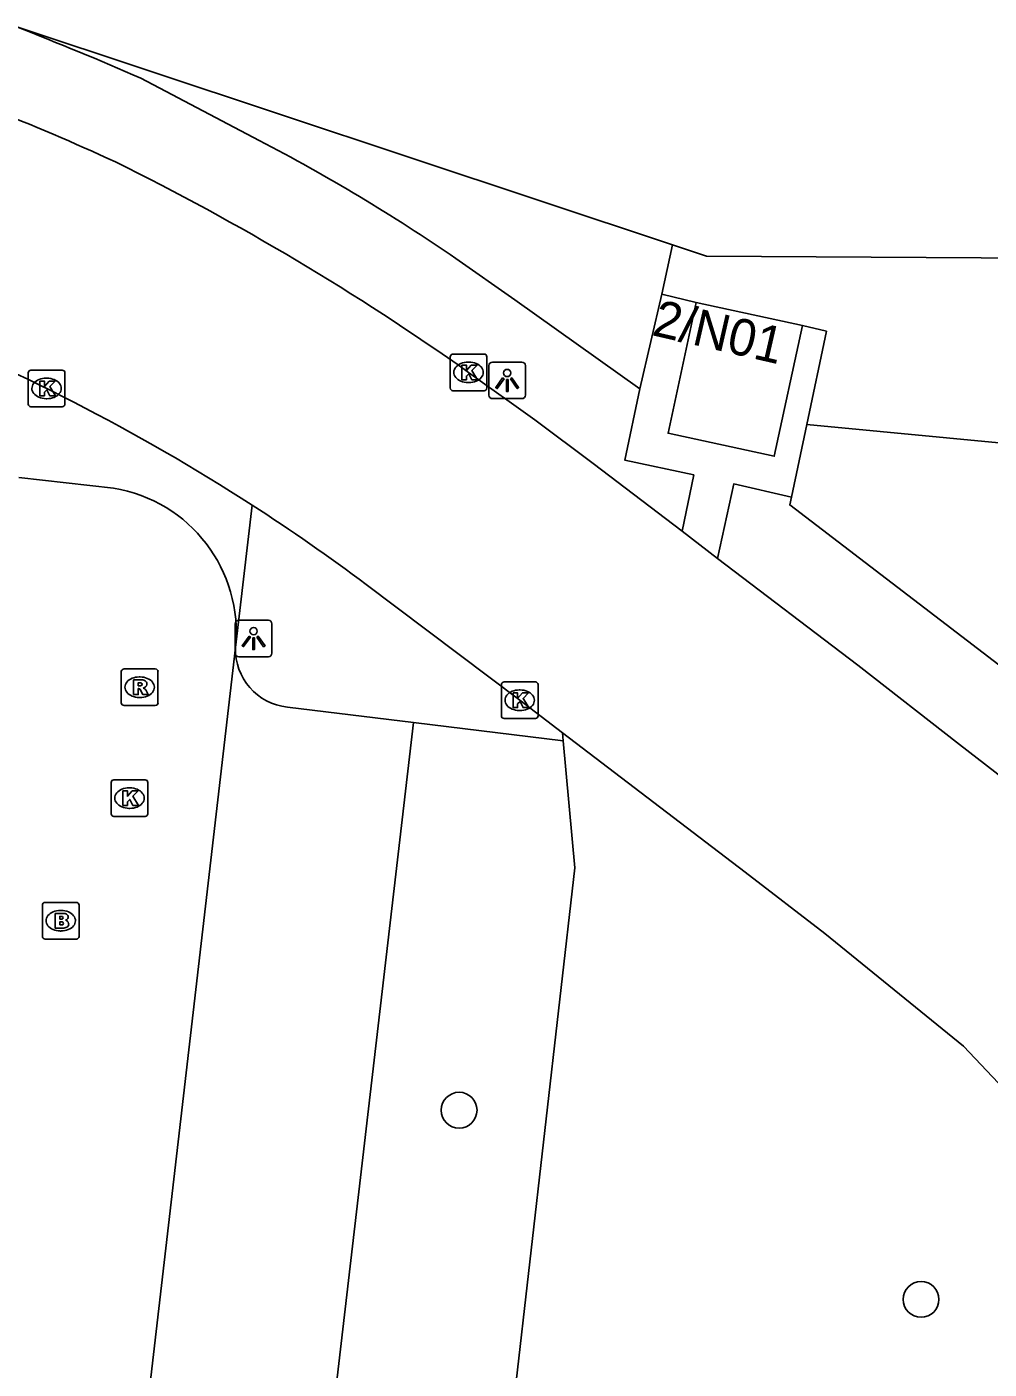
# Model space of a CAD drawing. Extents: x 161243 to 161752, y 384138 to 384885.
# Drawn here: x 161599.29 to 161625.54, y 384599.27 to 384635.9 of the extents above; entities that cross this region are included whole.
import ezdxf

# ---------------------------------------------------------------- set-up
doc = ezdxf.new("R2010")
doc.units = 0
for name, color, linetype in [('IMGEO_Boom', 7, 'Continuous'), ('IMGEO_Brandkraan', 7, 'Continuous'), ('IMGEO_Groenvoorziening', 7, 'Continuous'), ('IMGEO_Hek', 7, 'Continuous'), ('IMGEO_Kolk', 7, 'Continuous'), ('IMGEO_Lichtpunt', 7, 'Continuous'), ('IMGEO_Pand', 7, 'Continuous'), ('IMGEO_Pand_nummerreeks', 7, 'Continuous'), ('IMGEO_Parkeervlak_open', 7, 'Continuous'), ('IMGEO_Rijbaan_lokaal_open', 7, 'Continuous'), ('IMGEO_Rioolput', 7, 'Continuous'), ('IMGEO_Voetpad_open', 7, 'Continuous')]:
    doc.layers.add(name, color=color, linetype=linetype)

msp = doc.modelspace()

# ---------------------------------------------------------------- linework, layer by layer
at = {"layer": 'IMGEO_Boom'}
for centre in [(161611.081, 384606.338), (161623.685, 384601.176)]:
    msp.add_circle(centre, 0.489, dxfattribs=at)
at = {"layer": 'IMGEO_Brandkraan'}
for p, q in [((161599.787, 384612.008), (161600.639, 384612.008)), ((161599.712, 384611.082), (161599.712, 384611.934)), ((161600.2, 384611.788), (161600.225, 384611.788)), ((161600.713, 384611.934), (161600.713, 384611.082)), ((161600.639, 384611.008), (161599.787, 384611.008)), ((161600.223, 384611.228), (161600.198, 384611.228))]:
    msp.add_line(p, q, dxfattribs=at)
for points in [[(161599.787, 384612.008), (161600.639, 384612.008)], [(161599.712, 384611.082), (161599.712, 384611.934)], [(161600.06, 384611.708), (161600.06, 384611.308), (161600.273, 384611.308)], [(161600.291, 384611.708), (161600.06, 384611.708)], [(161600.239, 384611.627), (161600.185, 384611.627), (161600.185, 384611.551)], [(161600.713, 384611.934), (161600.713, 384611.082)], [(161600.185, 384611.551), (161600.238, 384611.551)], [(161600.247, 384611.475), (161600.185, 384611.475), (161600.185, 384611.394)], [(161600.185, 384611.394), (161600.247, 384611.394)], [(161600.639, 384611.008), (161599.787, 384611.008)]]:
    msp.add_lwpolyline(points, dxfattribs=at)
for centre, radius, start, end in [((161599.789, 384611.932), 0.0765, 91.552, 178.448), ((161599.789, 384611.932), 0.0765, 91.552, 178.448), ((161600.637, 384611.932), 0.0765, 1.552, 88.448), ((161600.637, 384611.932), 0.0765, 1.552, 88.448), ((161600.24, 384611.589), 0.0379, 267.8285, 90.9355), ((161600.295, 384611.563), 0.145, 59.4692, 91.5367), ((161600.32, 384611.61), 0.0922, 285.5137, 58.1501), ((161600.248, 384611.434), 0.0404, 269.8759, 90.5077), ((161600.279, 384611.559), 0.251, 268.6676, 293.5347), ((161600.325, 384611.418), 0.105, 301.3115, 78.989), ((161599.789, 384611.084), 0.0765, 181.552, 268.448), ((161599.789, 384611.084), 0.0765, 181.552, 268.448), ((161600.637, 384611.084), 0.0765, 271.552, 358.448), ((161600.637, 384611.084), 0.0765, 271.552, 358.448)]:
    msp.add_arc(centre, radius, start, end, dxfattribs=at)
for centre, major_axis, ratio, start_param, end_param in [((161600.199, 384611.508), (-0.387, 0.002), 0.722429, 4.712389, 7.853982), ((161600.224, 384611.508), (-0.39, 0.002), 0.717154, 1.570796, 4.712389)]:
    msp.add_ellipse(centre, major_axis=major_axis, ratio=ratio, start_param=start_param, end_param=end_param, dxfattribs=at)
at = {"layer": 'IMGEO_Groenvoorziening'}
for points in [[(161616.903, 384629.956), (161599.011, 384635.9)], [(161616.611, 384628.604), (161616.903, 384629.956)], [(161649.293, 384629.449), (161617.828, 384629.647), (161616.903, 384629.956)], [(161620.569, 384625.051), (161632.188, 384623.942), (161646.68, 384624.454)], [(161605.435, 384622.848), (161604.979, 384618.961)], [(161613.925, 384616.415), (161609.841, 384616.919)], [(161612.189, 384595.037), (161614.238, 384612.956), (161613.925, 384616.415)], [(161613.925, 384616.415), (161613.905, 384616.634)]]:
    msp.add_lwpolyline(points, dxfattribs=at)
at = {"layer": 'IMGEO_Hek'}
for points in [[(161599.011, 384635.9), (161616.903, 384629.956)], [(161616.903, 384629.956), (161617.828, 384629.647), (161649.293, 384629.449)]]:
    msp.add_lwpolyline(points, dxfattribs=at)
at = {"layer": 'IMGEO_Kolk'}
for p, q in [((161610.838, 384626.046), (161610.838, 384626.898)), ((161610.913, 384626.972), (161611.765, 384626.972)), ((161611.326, 384626.752), (161611.351, 384626.752)), ((161611.839, 384626.898), (161611.839, 384626.046)), ((161599.325, 384625.607), (161599.325, 384626.459)), ((161599.4, 384626.533), (161600.252, 384626.533)), ((161599.813, 384626.313), (161599.838, 384626.313)), ((161600.326, 384626.459), (161600.326, 384625.607)), ((161611.765, 384625.972), (161610.913, 384625.972)), ((161611.349, 384626.192), (161611.324, 384626.192)), ((161600.252, 384625.533), (161599.4, 384625.533)), ((161599.836, 384625.753), (161599.811, 384625.753)), ((161612.235, 384617.1), (161612.235, 384617.952)), ((161612.31, 384618.026), (161613.162, 384618.026)), ((161613.236, 384617.952), (161613.236, 384617.1)), ((161612.723, 384617.806), (161612.748, 384617.806)), ((161612.746, 384617.246), (161612.721, 384617.246)), ((161613.162, 384617.026), (161612.31, 384617.026)), ((161601.588, 384614.428), (161601.588, 384615.28)), ((161601.663, 384615.354), (161602.515, 384615.354)), ((161602.589, 384615.28), (161602.589, 384614.428)), ((161602.076, 384615.134), (161602.101, 384615.134)), ((161602.099, 384614.574), (161602.074, 384614.574)), ((161602.515, 384614.354), (161601.663, 384614.354))]:
    msp.add_line(p, q, dxfattribs=at)
for points in [[(161610.838, 384626.046), (161610.838, 384626.898)], [(161610.913, 384626.972), (161611.765, 384626.972)], [(161611.159, 384626.672), (161611.282, 384626.672), (161611.282, 384626.521), (161611.412, 384626.672), (161611.576, 384626.672), (161611.43, 384626.521), (161611.583, 384626.272), (161611.431, 384626.272), (161611.346, 384626.436), (161611.282, 384626.369), (161611.282, 384626.272), (161611.159, 384626.272), (161611.159, 384626.672)], [(161611.839, 384626.898), (161611.839, 384626.046)], [(161599.325, 384625.607), (161599.325, 384626.459)], [(161599.4, 384626.533), (161600.252, 384626.533)], [(161600.326, 384626.459), (161600.326, 384625.607)], [(161599.646, 384626.233), (161599.769, 384626.233), (161599.769, 384626.082), (161599.899, 384626.233), (161600.063, 384626.233), (161599.917, 384626.082), (161600.07, 384625.833), (161599.918, 384625.833), (161599.833, 384625.997), (161599.769, 384625.93), (161599.769, 384625.833), (161599.646, 384625.833), (161599.646, 384626.233)], [(161611.765, 384625.972), (161610.913, 384625.972)], [(161600.252, 384625.533), (161599.4, 384625.533)], [(161612.235, 384617.1), (161612.235, 384617.952)], [(161612.31, 384618.026), (161613.162, 384618.026)], [(161613.236, 384617.952), (161613.236, 384617.1)], [(161612.556, 384617.726), (161612.679, 384617.726), (161612.679, 384617.575), (161612.809, 384617.726), (161612.973, 384617.726), (161612.827, 384617.575), (161612.98, 384617.326), (161612.828, 384617.326), (161612.743, 384617.49), (161612.679, 384617.423), (161612.679, 384617.326), (161612.556, 384617.326), (161612.556, 384617.726)], [(161613.162, 384617.026), (161612.31, 384617.026)], [(161601.588, 384614.428), (161601.588, 384615.28)], [(161601.663, 384615.354), (161602.515, 384615.354)], [(161602.589, 384615.28), (161602.589, 384614.428)], [(161601.909, 384615.054), (161602.032, 384615.054), (161602.032, 384614.903), (161602.162, 384615.054), (161602.326, 384615.054), (161602.18, 384614.903), (161602.333, 384614.654), (161602.181, 384614.654), (161602.096, 384614.818), (161602.032, 384614.751), (161602.032, 384614.654), (161601.909, 384614.654), (161601.909, 384615.054)], [(161602.515, 384614.354), (161601.663, 384614.354)]]:
    msp.add_lwpolyline(points, dxfattribs=at)
for centre, start, end in [((161610.915, 384626.896), 91.552, 178.448), ((161610.915, 384626.896), 91.552, 178.448), ((161611.763, 384626.896), 1.552, 88.448), ((161611.763, 384626.896), 1.552, 88.448), ((161599.402, 384626.457), 91.552, 178.448), ((161599.402, 384626.457), 91.552, 178.448), ((161600.25, 384626.457), 1.552, 88.448), ((161600.25, 384626.457), 1.552, 88.448), ((161610.915, 384626.048), 181.552, 268.448), ((161610.915, 384626.048), 181.552, 268.448), ((161611.763, 384626.048), 271.552, 358.448), ((161611.763, 384626.048), 271.552, 358.448), ((161599.402, 384625.609), 181.552, 268.448), ((161599.402, 384625.609), 181.552, 268.448), ((161600.25, 384625.609), 271.552, 358.448), ((161600.25, 384625.609), 271.552, 358.448), ((161612.312, 384617.95), 91.552, 178.448), ((161612.312, 384617.95), 91.552, 178.448), ((161613.16, 384617.95), 1.552, 88.448), ((161613.16, 384617.95), 1.552, 88.448), ((161612.312, 384617.102), 181.552, 268.448), ((161612.312, 384617.102), 181.552, 268.448), ((161613.16, 384617.102), 271.552, 358.448), ((161613.16, 384617.102), 271.552, 358.448), ((161601.665, 384615.278), 91.552, 178.448), ((161601.665, 384615.278), 91.552, 178.448), ((161602.513, 384615.278), 1.552, 88.448), ((161602.513, 384615.278), 1.552, 88.448), ((161601.665, 384614.43), 181.552, 268.448), ((161601.665, 384614.43), 181.552, 268.448), ((161602.513, 384614.43), 271.552, 358.448), ((161602.513, 384614.43), 271.552, 358.448)]:
    msp.add_arc(centre, 0.0765, start, end, dxfattribs=at)
for centre, major_axis, ratio, start_param, end_param in [((161611.325, 384626.472), (-0.387, 0.002), 0.722429, 4.712389, 7.853982), ((161611.35, 384626.472), (-0.39, 0.002), 0.717154, 1.570796, 4.712389), ((161599.812, 384626.033), (-0.387, 0.002), 0.722429, 4.712389, 7.853982), ((161599.837, 384626.033), (-0.39, 0.002), 0.717154, 1.570796, 4.712389), ((161612.722, 384617.526), (-0.387, 0.002), 0.722429, 4.712389, 7.853982), ((161612.747, 384617.526), (-0.39, 0.002), 0.717154, 1.570796, 4.712389), ((161602.075, 384614.854), (-0.387, 0.002), 0.722429, 4.712389, 7.853982), ((161602.1, 384614.854), (-0.39, 0.002), 0.717154, 1.570796, 4.712389)]:
    msp.add_ellipse(centre, major_axis=major_axis, ratio=ratio, start_param=start_param, end_param=end_param, dxfattribs=at)
at = {"layer": 'IMGEO_Lichtpunt'}
for p, q in [((161611.895, 384626.657), (161611.895, 384625.85)), ((161611.895, 384626.657), (161611.895, 384625.85)), ((161612.797, 384626.752), (161611.989, 384626.752)), ((161612.797, 384626.752), (161611.989, 384626.752)), ((161612.891, 384625.85), (161612.891, 384626.657)), ((161612.891, 384625.85), (161612.891, 384626.657)), ((161611.989, 384625.756), (161612.797, 384625.756)), ((161611.989, 384625.756), (161612.797, 384625.756)), ((161605.877, 384619.708), (161605.069, 384619.708)), ((161605.877, 384619.708), (161605.069, 384619.708)), ((161604.975, 384619.613), (161604.975, 384618.806)), ((161604.975, 384619.613), (161604.975, 384618.806)), ((161605.971, 384618.806), (161605.971, 384619.613)), ((161605.971, 384618.806), (161605.971, 384619.613)), ((161605.069, 384618.712), (161605.877, 384618.712)), ((161605.069, 384618.712), (161605.877, 384618.712))]:
    msp.add_line(p, q, dxfattribs=at)
for points in [[(161612.269, 384626.321), (161612.308, 384626.293), (161612.12, 384626.031), (161612.082, 384626.058), (161612.269, 384626.321)], [(161612.371, 384626.273), (161612.418, 384626.273), (161612.418, 384625.951), (161612.371, 384625.951), (161612.371, 384626.273)], [(161612.481, 384626.293), (161612.519, 384626.32), (161612.706, 384626.058), (161612.667, 384626.03), (161612.481, 384626.293)], [(161605.349, 384619.277), (161605.388, 384619.249), (161605.2, 384618.987), (161605.162, 384619.014), (161605.349, 384619.277)], [(161605.451, 384619.229), (161605.498, 384619.229), (161605.498, 384618.907), (161605.451, 384618.907), (161605.451, 384619.229)], [(161605.561, 384619.249), (161605.599, 384619.276), (161605.786, 384619.014), (161605.747, 384618.986), (161605.561, 384619.249)]]:
    msp.add_lwpolyline(points, dxfattribs=at)
for centre in [(161612.394, 384626.455), (161605.474, 384619.411)]:
    msp.add_circle(centre, 0.0994, dxfattribs=at)
for centre, start, end in [((161611.989, 384626.657), 90, 180), ((161611.989, 384626.657), 90, 180), ((161612.797, 384626.657), 0, 90), ((161612.797, 384626.657), 0, 90), ((161611.989, 384625.85), 180, 270), ((161611.989, 384625.85), 180, 270), ((161612.797, 384625.85), 270, 0), ((161612.797, 384625.85), 270, 360), ((161605.069, 384619.613), 90, 180), ((161605.069, 384619.613), 90, 180), ((161605.877, 384619.613), 0, 90), ((161605.877, 384619.613), 0, 90), ((161605.069, 384618.806), 180, 270), ((161605.069, 384618.806), 180, 270), ((161605.877, 384618.806), 270, 0), ((161605.877, 384618.806), 270, 360)]:
    msp.add_arc(centre, 0.0946, start, end, dxfattribs=at)
at = {"layer": 'IMGEO_Pand'}
for points in [[(161620.45, 384627.751), (161619.679, 384624.183), (161616.782, 384624.81), (161617.553, 384628.377)], [(161617.553, 384628.377), (161620.45, 384627.751)]]:
    msp.add_lwpolyline(points, dxfattribs=at)
at = {"layer": 'IMGEO_Parkeervlak_open'}
for points in [[(161609.841, 384616.919), (161606.397, 384617.334)], [(161607.21, 384594.349), (161609.841, 384616.919)]]:
    msp.add_lwpolyline(points, dxfattribs=at)
msp.add_arc((161606.573, 384618.919), 1.594, 178.481, 263.6661, dxfattribs=at)
at = {"layer": 'IMGEO_Rijbaan_lokaal_open'}
for points in [[(161611.339, 384626.472), (161613.148, 384625.176), (161614.74, 384623.986), (161617.165, 384622.136)], [(161601.653, 384623.311), (161599.071, 384623.606)], [(161617.165, 384622.136), (161618.136, 384621.395)], [(161618.136, 384621.395), (161621.959, 384618.479), (161624.731, 384616.32), (161627.429, 384614.233)], [(161613.905, 384616.634), (161612.736, 384617.526), (161608.548, 384620.685)], [(161602.142, 384594.492), (161604.979, 384618.961)], [(161633.111, 384597.461), (161628.766, 384603.455), (161626.747, 384606.076), (161624.845, 384608.084), (161621.062, 384611.158), (161618.885, 384612.836), (161613.905, 384616.634)]]:
    msp.add_lwpolyline(points, dxfattribs=at)
for centre, radius, start, end in [((161572.777, 384569.305), 69.242, 65.30581, 71.47138), ((161570.122, 384568.282), 71.308, 54.68946, 63.71069), ((161574.79, 384575.412), 56.473, 57.1366, 68.5414), ((161601.017, 384619.378), 3.984, 353.9918, 80.8111), ((161574.461, 384574.949), 57.042, 53.3032, 57.1115)]:
    msp.add_arc(centre, radius, start, end, dxfattribs=at)
at = {"layer": 'IMGEO_Rioolput'}
for p, q in [((161601.865, 384617.455), (161601.865, 384618.307)), ((161601.94, 384618.381), (161602.792, 384618.381)), ((161602.866, 384618.307), (161602.866, 384617.455)), ((161602.353, 384618.161), (161602.378, 384618.161)), ((161602.376, 384617.601), (161602.351, 384617.601)), ((161602.792, 384617.381), (161601.94, 384617.381))]:
    msp.add_line(p, q, dxfattribs=at)
for points in [[(161601.865, 384617.455), (161601.865, 384618.307)], [(161601.94, 384618.381), (161602.792, 384618.381)], [(161602.866, 384618.307), (161602.866, 384617.455)], [(161602.454, 384618.079), (161602.202, 384618.081), (161602.202, 384617.681)], [(161602.202, 384617.681), (161602.326, 384617.681), (161602.326, 384617.843), (161602.337, 384617.843)], [(161602.38, 384618), (161602.326, 384618), (161602.326, 384617.919)], [(161602.326, 384617.919), (161602.378, 384617.919)], [(161602.384, 384617.814), (161602.455, 384617.681), (161602.595, 384617.681), (161602.53, 384617.807)], [(161602.792, 384617.381), (161601.94, 384617.381)]]:
    msp.add_lwpolyline(points, dxfattribs=at)
for centre, radius, start, end in [((161601.942, 384618.305), 0.0765, 91.552, 178.448), ((161601.942, 384618.305), 0.0765, 91.552, 178.448), ((161602.79, 384618.305), 0.0765, 1.552, 88.448), ((161602.79, 384618.305), 0.0765, 1.552, 88.448), ((161602.336, 384617.79), 0.0533, 26.0293, 88.6989), ((161602.362, 384618.108), 0.19, 274.7715, 282.9687), ((161602.386, 384617.904), 0.0964, 77.0061, 93.1865), ((161602.4, 384617.961), 0.0378, 276.6634, 79.6772), ((161602.453, 384617.969), 0.109, 350.3612, 89.416), ((161602.451, 384617.969), 0.112, 277.5842, 350.9817), ((161602.435, 384617.754), 0.108, 29.5134, 73.7905), ((161601.942, 384617.457), 0.0765, 181.552, 268.448), ((161601.942, 384617.457), 0.0765, 181.552, 268.448), ((161602.79, 384617.457), 0.0765, 271.552, 358.448), ((161602.79, 384617.457), 0.0765, 271.552, 358.448)]:
    msp.add_arc(centre, radius, start, end, dxfattribs=at)
for centre, major_axis, ratio, start_param, end_param in [((161602.352, 384617.881), (-0.387, 0.002), 0.722429, 4.712389, 7.853982), ((161602.377, 384617.881), (-0.39, 0.002), 0.717154, 1.570796, 4.712389)]:
    msp.add_ellipse(centre, major_axis=major_axis, ratio=ratio, start_param=start_param, end_param=end_param, dxfattribs=at)
at = {"layer": 'IMGEO_Voetpad_open'}
for points in [[(161602.394, 384634.5), (161605.628, 384632.8)], [(161610.995, 384629.578), (161612.606, 384628.455), (161616.012, 384626.02)], [(161616.012, 384626.02), (161616.611, 384628.604)], [(161616.611, 384628.604), (161617.553, 384628.377)], [(161620.45, 384627.751), (161621.105, 384627.595), (161620.569, 384625.051)], [(161617.165, 384622.136), (161617.485, 384623.673), (161615.602, 384624.077), (161616.012, 384626.02)], [(161620.569, 384625.051), (161620.151, 384623.067)], [(161620.151, 384623.067), (161618.573, 384623.427), (161618.136, 384621.395)], [(161641.462, 384614.077), (161630.208, 384615.091), (161626.391, 384618.043), (161624.217, 384619.712), (161620.103, 384622.856), (161620.151, 384623.067)]]:
    msp.add_lwpolyline(points, dxfattribs=at)
for centre, radius, start, end in [((161566.214, 384551.862), 90.211, 66.35581, 68.68133), ((161581.737, 384586.923), 51.725, 55.553, 62.4913)]:
    msp.add_arc(centre, radius, start, end, dxfattribs=at)

# ---------------------------------------------------------------- texts
at = {"layer": 'IMGEO_Pand_nummerreeks'}
msp.add_text('2/N01', height=1, rotation=347.0424, dxfattribs=at).set_placement((161616.315, 384627.491))

doc.saveas('drawing.dxf')
